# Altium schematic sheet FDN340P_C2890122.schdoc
size 127 x 101 mm
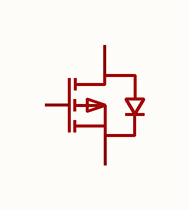
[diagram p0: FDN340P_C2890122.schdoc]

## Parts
Q?  fdn340p  [SOT-23-3_L2.9-W1.3-P1.90-LS2.4-BR]  (value not drawn)

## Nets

Not connected (* = marked no-connect by the designer): Q? 1(G) 2(S) 3(D)

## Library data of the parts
Q? = fdn340p: 数量:1个P沟道;漏源电压(Vdss):20V;连续漏极电流(Id):2A;导通电阻(RDS(on)):210mΩ@1.8V;耗散功率(Pd):1.1W;阈值电压(Vgs(th)):1.5V;; Manufacturer: TECH PUBLIC(台舟); Symbol: FDN340P_C2890122; AddInBom: yes; ModelId: c62791f0466c4ae2a892c056b845b0ca; ModelName: SOT-23-3P_L2.9-W1.3-H1.0-LS2.4-P0.95; ModelTransform: 98.425,114.173,0,180,0,0,0.0005,-0.0005,0; Number: 1个P沟道; Drain to Source Voltage: 20V; Current - Continuous Drain(Id): 2A; Pd - Power Dissipation: 1.1W; Gate Threshold Voltage (Vgs(th)): 1.5V; Gate Charge(Qg): 8nC@4.5V; Input Capacitance(Ciss): 600pF; Reverse Transfer Capacitance (Crss@Vds): 80pF; Type: P沟道; Output Capacitance(Coss): 175pF; Vgs: ±8V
